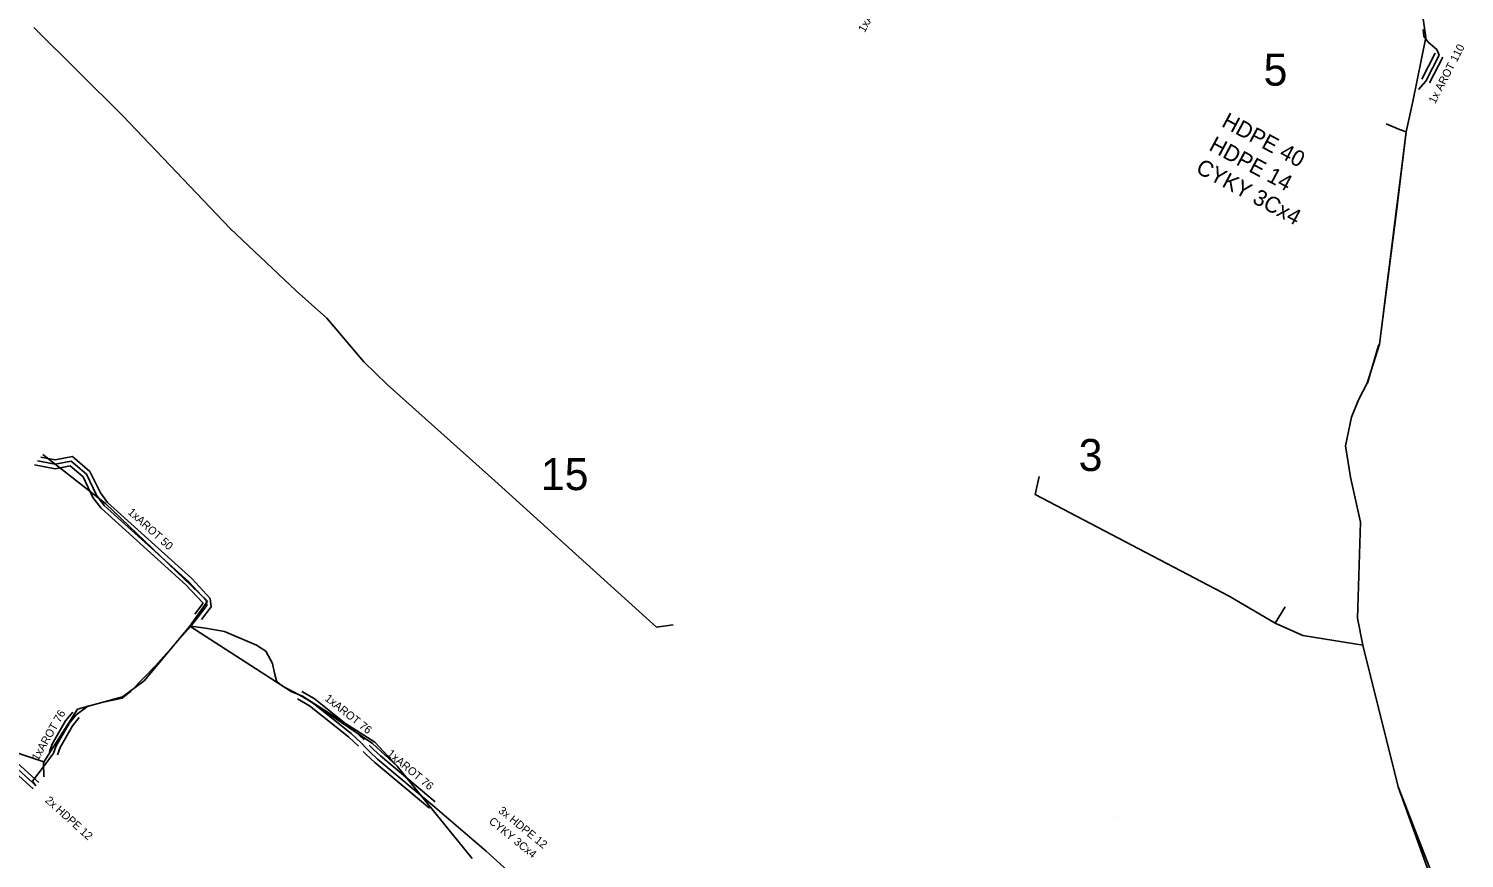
# Model space of a CAD drawing. Extents: x -651943 to -618711, y -1138561 to -1100552.
# Drawn here: x -642611.4 to -642476.9, y -1114571.9 to -1114494.1 of the extents above; entities that cross this region are included whole.
import ezdxf

# ---------------------------------------------------------------- set-up
doc = ezdxf.new("R2010")
doc.units = 0
for name, color, linetype in [('KT optika', 7, 'Continuous'), ('KT trasa', 7, 'Continuous'), ('KT zařízení', 7, 'Continuous'), ('SATT bloky', 7, 'Continuous'), ('SATT stanice', 7, 'Continuous')]:
    doc.layers.add(name, color=color, linetype=linetype)

# ---------------------------------------------------------------- blocks, each defined once
blk = doc.blocks.new('POINT_DISPLAY')
blk.add_line((0, 0), (0, 0))

msp = doc.modelspace()

# ---------------------------------------------------------------- linework, layer by layer
at = {"layer": 'KT optika'}
for p, q in [((-642610.92, -1114493.97), (-642602.59, -1114502.26)), ((-642602.59, -1114502.26), (-642592.51, -1114512.8)), ((-642484.19, -1114502.99), (-642482.93, -1114503.53)), ((-642586.34, -1114518.67), (-642592.51, -1114512.8)), ((-642583.47, -1114521.23), (-642586.34, -1114518.67)), ((-642580.01, -1114525.3), (-642583.47, -1114521.23)), ((-642577.82, -1114527.45), (-642580.01, -1114525.3)), ((-642567.73, -1114536.48), (-642577.82, -1114527.45)), ((-642608.93, -1114534.92), (-642610.57, -1114534.61)), ((-642607.42, -1114534.63), (-642608.93, -1114534.92)), ((-642605.98, -1114535.86), (-642607.42, -1114534.63)), ((-642605.04, -1114537.81), (-642605.98, -1114535.86)), ((-642552.57, -1114550.18), (-642567.73, -1114536.48)), ((-642604.32, -1114538.77), (-642605.04, -1114537.81)), ((-642596.41, -1114545.93), (-642604.32, -1114538.77)), ((-642594.77, -1114547.68), (-642596.41, -1114545.93)), ((-642595.53, -1114549.22), (-642594.72, -1114548.16)), ((-642594.72, -1114548.16), (-642594.77, -1114547.68)), ((-642494.6, -1114549.81), (-642493.66, -1114548.28)), ((-642596.22, -1114550.08), (-642595.53, -1114549.22)), ((-642596.22, -1114550.08), (-642599.52, -1114553.8)), ((-642594.82, -1114550.29), (-642596.22, -1114550.08)), ((-642593.07, -1114550.58), (-642594.82, -1114550.29)), ((-642590.05, -1114551.87), (-642593.07, -1114550.58)), ((-642551.02, -1114549.98), (-642552.57, -1114550.18)), ((-642492, -1114550.98), (-642494.6, -1114549.81)), ((-642486.39, -1114551.88), (-642492, -1114550.98)), ((-642589.18, -1114552.43), (-642590.05, -1114551.87)), ((-642588.55, -1114553.6), (-642589.18, -1114552.43)), ((-642588.36, -1114554.5), (-642588.55, -1114553.6)), ((-642599.52, -1114553.8), (-642601.83, -1114556.19)), ((-642588.19, -1114555.23), (-642588.36, -1114554.5)), ((-642601.83, -1114556.19), (-642602.64, -1114556.84)), ((-642587.62, -1114555.72), (-642588.19, -1114555.23)), ((-642586.01, -1114556.56), (-642587.62, -1114555.72)), ((-642605.86, -1114557.59), (-642606.97, -1114558.4)), ((-642604.28, -1114557.2), (-642605.86, -1114557.59)), ((-642602.64, -1114556.84), (-642604.28, -1114557.2)), ((-642584.87, -1114557.22), (-642586.01, -1114556.56)), ((-642581.17, -1114560.17), (-642584.87, -1114557.22)), ((-642606.97, -1114558.4), (-642607.62, -1114559.21)), ((-642607.62, -1114559.21), (-642608.83, -1114561.32)), ((-642580.23, -1114561.05), (-642581.17, -1114560.17)), ((-642608.83, -1114561.32), (-642609.08, -1114562.01)), ((-642579.78, -1114561.54), (-642580.23, -1114561.05)), ((-642579.44, -1114561.87), (-642579.78, -1114561.54)), ((-642609.08, -1114562.01), (-642610.04, -1114563.3)), ((-642578.71, -1114562.57), (-642579.44, -1114561.87)), ((-642573.57, -1114566.86), (-642578.71, -1114562.57)), ((-642610.04, -1114563.3), (-642611.05, -1114564.61)), ((-642611.05, -1114564.61), (-642610.74, -1114565.06)), ((-642568.52, -1114571.19), (-642573.57, -1114566.86)), ((-642561.43, -1114577.62), (-642568.52, -1114571.19))]:
    msp.add_line(p, q, dxfattribs=at)
msp.add_lwpolyline([(-642479.3, -1114574.88), (-642483.08, -1114565.15), (-642486.39, -1114551.88), (-642486.87, -1114549.35), (-642486.59, -1114540.36), (-642487.54, -1114536.13), (-642487.99, -1114533.19), (-642487.45, -1114530.51), (-642486.8, -1114528.89), (-642485.96, -1114527.32), (-642484.82, -1114523.65), (-642482.31, -1114503.76), (-642481.68, -1114500.92), (-642480.48, -1114494.91), (-642480.84, -1114492.27)], dxfattribs=at)
at = {"layer": 'KT trasa'}
for p, q in [((-642480.48, -1114494.91), (-642480.84, -1114492.27)), ((-642610.92, -1114493.97), (-642602.59, -1114502.26)), ((-642480.67, -1114494.78), (-642480.74, -1114494.17)), ((-642481.68, -1114500.92), (-642480.48, -1114494.91)), ((-642480.27, -1114495.36), (-642480.67, -1114494.78)), ((-642479.46, -1114496.03), (-642480.27, -1114495.36)), ((-642480.48, -1114498.99), (-642479.23, -1114496.57)), ((-642479.23, -1114496.57), (-642479.46, -1114496.03)), ((-642481.15, -1114499.8), (-642480.48, -1114498.99)), ((-642482.31, -1114503.76), (-642481.68, -1114500.92)), ((-642602.59, -1114502.26), (-642592.51, -1114512.8)), ((-642484.19, -1114502.99), (-642482.93, -1114503.53)), ((-642483.27, -1114511.47), (-642482.31, -1114503.76)), ((-642482.31, -1114503.76), (-642482.93, -1114503.53)), ((-642484.82, -1114523.65), (-642483.27, -1114511.47)), ((-642586.34, -1114518.67), (-642592.51, -1114512.8)), ((-642583.47, -1114521.23), (-642586.34, -1114518.67)), ((-642580.01, -1114525.3), (-642583.47, -1114521.23)), ((-642485.95, -1114527.31), (-642484.9, -1114523.78)), ((-642484.9, -1114523.78), (-642484.82, -1114523.65)), ((-642577.82, -1114527.45), (-642580.01, -1114525.3)), ((-642567.73, -1114536.48), (-642577.82, -1114527.45)), ((-642486.8, -1114528.89), (-642485.96, -1114527.32)), ((-642487.45, -1114530.51), (-642486.8, -1114528.89)), ((-642487.99, -1114533.19), (-642487.45, -1114530.51)), ((-642487.54, -1114536.13), (-642487.99, -1114533.19)), ((-642608.93, -1114534.92), (-642610.57, -1114534.61)), ((-642604.2, -1114538.58), (-642610.08, -1114534.01)), ((-642607.42, -1114534.63), (-642608.93, -1114534.92)), ((-642605.98, -1114535.86), (-642607.42, -1114534.63)), ((-642605.04, -1114537.81), (-642605.98, -1114535.86)), ((-642517.08, -1114537.75), (-642516.71, -1114536.06)), ((-642486.59, -1114540.36), (-642487.54, -1114536.13)), ((-642552.57, -1114550.18), (-642567.73, -1114536.48)), ((-642604.32, -1114538.77), (-642605.04, -1114537.81)), ((-642596.41, -1114545.93), (-642604.32, -1114538.77)), ((-642594.65, -1114547.76), (-642604.2, -1114538.58)), ((-642498.91, -1114547.27), (-642517.08, -1114537.75)), ((-642486.87, -1114549.35), (-642486.59, -1114540.36)), ((-642594.77, -1114547.68), (-642596.41, -1114545.93)), ((-642596.3, -1114550.1), (-642594.65, -1114547.76)), ((-642595.53, -1114549.22), (-642594.72, -1114548.16)), ((-642594.72, -1114548.16), (-642594.77, -1114547.68)), ((-642494.6, -1114549.81), (-642498.91, -1114547.27)), ((-642494.6, -1114549.81), (-642493.66, -1114548.28)), ((-642596.22, -1114550.08), (-642595.53, -1114549.22)), ((-642486.39, -1114551.88), (-642486.87, -1114549.35)), ((-642600.57, -1114555.22), (-642596.3, -1114550.1)), ((-642596.22, -1114550.08), (-642599.52, -1114553.8)), ((-642596.3, -1114550.1), (-642586.81, -1114556.23)), ((-642594.82, -1114550.29), (-642596.22, -1114550.08)), ((-642593.07, -1114550.58), (-642594.82, -1114550.29)), ((-642590.05, -1114551.87), (-642593.07, -1114550.58)), ((-642551.02, -1114549.98), (-642552.57, -1114550.18)), ((-642492, -1114550.98), (-642494.6, -1114549.81)), ((-642486.39, -1114551.88), (-642492, -1114550.98)), ((-642589.18, -1114552.43), (-642590.05, -1114551.87)), ((-642483.08, -1114565.15), (-642486.39, -1114551.88)), ((-642588.55, -1114553.6), (-642589.18, -1114552.43)), ((-642588.36, -1114554.5), (-642588.55, -1114553.6)), ((-642599.52, -1114553.8), (-642601.83, -1114556.19)), ((-642588.19, -1114555.23), (-642588.36, -1114554.5)), ((-642601.83, -1114556.19), (-642602.64, -1114556.84)), ((-642602.61, -1114556.72), (-642600.57, -1114555.22)), ((-642587.62, -1114555.72), (-642588.19, -1114555.23)), ((-642586.01, -1114556.56), (-642587.62, -1114555.72)), ((-642586.81, -1114556.23), (-642585.76, -1114556.65)), ((-642605.86, -1114557.59), (-642606.97, -1114558.4)), ((-642606.82, -1114557.86), (-642602.61, -1114556.72)), ((-642604.28, -1114557.2), (-642605.86, -1114557.59)), ((-642602.64, -1114556.84), (-642604.28, -1114557.2)), ((-642584.87, -1114557.22), (-642586.01, -1114556.56)), ((-642585.76, -1114556.65), (-642578.96, -1114560.98)), ((-642579.18, -1114561.09), (-642585.76, -1114556.65)), ((-642581.17, -1114560.17), (-642584.87, -1114557.22)), ((-642610.02, -1114562.86), (-642606.82, -1114557.86)), ((-642606.97, -1114558.4), (-642607.62, -1114559.21)), ((-642607.62, -1114559.21), (-642608.83, -1114561.32)), ((-642580.23, -1114561.05), (-642581.17, -1114560.17)), ((-642610.72, -1114565.04), (-642614.45, -1114561.68)), ((-642608.83, -1114561.32), (-642609.08, -1114562.01)), ((-642579.78, -1114561.54), (-642580.23, -1114561.05)), ((-642579.44, -1114561.87), (-642579.78, -1114561.54)), ((-642579.18, -1114561.09), (-642576.88, -1114563.23)), ((-642576.88, -1114563.23), (-642578.96, -1114560.98)), ((-642609.08, -1114562.01), (-642610.04, -1114563.3)), ((-642610.02, -1114562.86), (-642609.98, -1114564.21)), ((-642578.71, -1114562.57), (-642579.44, -1114561.87)), ((-642573.57, -1114566.86), (-642578.71, -1114562.57)), ((-642610.04, -1114563.3), (-642611.05, -1114564.61)), ((-642576.88, -1114563.23), (-642569.84, -1114571.89)), ((-642611.05, -1114564.61), (-642610.74, -1114565.06)), ((-642479.66, -1114574.63), (-642483.08, -1114565.15)), ((-642568.52, -1114571.19), (-642573.57, -1114566.86)), ((-642561.43, -1114577.62), (-642568.52, -1114571.19))]:
    msp.add_line(p, q, dxfattribs=at)
msp.add_lwpolyline([(-642609.89, -1114562.84), (-642619.45, -1114559.65), (-642643.97, -1114559.65)], dxfattribs=at)
at = {"layer": 'KT zařízení'}
for p, q in [((-642480.84, -1114498.81), (-642479.59, -1114496.39)), ((-642480.12, -1114499.17), (-642478.87, -1114496.75)), ((-642608.93, -1114534.51), (-642610.28, -1114534.26)), ((-642607.31, -1114534.2), (-642608.93, -1114534.51)), ((-642605.66, -1114535.61), (-642607.31, -1114534.2)), ((-642608.93, -1114535.33), (-642610.86, -1114534.96)), ((-642607.53, -1114535.06), (-642608.93, -1114535.33)), ((-642606.3, -1114536.11), (-642607.53, -1114535.06)), ((-642605.38, -1114538.02), (-642606.3, -1114536.11)), ((-642604.69, -1114537.6), (-642605.66, -1114535.61)), ((-642604.03, -1114538.5), (-642604.69, -1114537.6)), ((-642604.62, -1114539.04), (-642605.38, -1114538.02)), ((-642596.13, -1114545.64), (-642604.03, -1114538.5)), ((-642596.69, -1114546.22), (-642604.62, -1114539.04)), ((-642594.39, -1114547.5), (-642596.13, -1114545.64)), ((-642595.06, -1114547.95), (-642596.69, -1114546.22)), ((-642595.85, -1114548.98), (-642595.06, -1114547.95)), ((-642595.21, -1114549.46), (-642594.31, -1114548.28)), ((-642594.31, -1114548.28), (-642594.39, -1114547.5)), ((-642584.65, -1114556.89), (-642585.81, -1114556.21)), ((-642585.09, -1114557.55), (-642586.21, -1114556.91)), ((-642581.44, -1114560.47), (-642585.09, -1114557.55)), ((-642580.9, -1114559.87), (-642584.65, -1114556.89)), ((-642607.95, -1114558.98), (-642609.2, -1114561.16)), ((-642607.28, -1114558.15), (-642607.95, -1114558.98)), ((-642606.66, -1114558.65), (-642607.29, -1114559.44)), ((-642607.29, -1114559.44), (-642608.46, -1114561.48)), ((-642580.5, -1114561.34), (-642581.44, -1114560.47)), ((-642579.96, -1114560.76), (-642580.9, -1114559.87)), ((-642609.2, -1114561.16), (-642609.46, -1114561.87)), ((-642608.46, -1114561.48), (-642608.7, -1114562.15)), ((-642579.8, -1114562.08), (-642580.06, -1114561.83)), ((-642579.08, -1114561.66), (-642579.5, -1114561.25)), ((-642578.45, -1114562.26), (-642579.08, -1114561.66)), ((-642578.97, -1114562.88), (-642579.8, -1114562.08)), ((-642573.83, -1114567.17), (-642578.97, -1114562.88)), ((-642573.31, -1114566.55), (-642578.45, -1114562.26))]:
    msp.add_line(p, q, dxfattribs=at)
for points in [[(-642610.45, -1114564.74), (-642614.19, -1114561.37), (-642616.18, -1114559.85), (-642618.38, -1114557.95), (-642618.97, -1114557.75), (-642620.2, -1114557.28), (-642621.06, -1114557.2), (-642622.77, -1114557.96), (-642630.99, -1114560.06), (-642636.21, -1114561.32), (-642638.26, -1114561.61), (-642641.58, -1114562.54), (-642642.72, -1114562.76), (-642642.9, -1114560.4), (-642643.24, -1114556.07), (-642643.37, -1114553.13), (-642643.98, -1114552.64), (-642645.11, -1114552.72)], [(-642610.99, -1114565.33), (-642614.71, -1114561.99), (-642616.68, -1114560.47), (-642618.78, -1114558.66), (-642619.23, -1114558.51), (-642620.38, -1114558.06), (-642620.92, -1114558.02), (-642622.51, -1114558.72), (-642630.79, -1114560.84), (-642636.06, -1114562.1), (-642638.1, -1114562.39), (-642641.4, -1114563.32), (-642642.86, -1114563.6), (-642643.48, -1114563.36), (-642643.7, -1114560.46), (-642644.04, -1114556.11), (-642644.15, -1114553.53), (-642644.24, -1114553.46), (-642645.06, -1114553.51)]]:
    msp.add_lwpolyline(points, dxfattribs=at)

# ---------------------------------------------------------------- block references
at = {"layer": 'SATT stanice'}
msp.add_blockref('POINT_DISPLAY', (-642509.61, -1114567.97), dxfattribs=at)

# ---------------------------------------------------------------- texts
at = {"layer": 'KT zařízení'}
for s, height, rotation, p in [('1xAROT 40', 0.75, 60.3363, (-642533.07, -1114494.5)), ('1x AROT 110', 0.75, 62.6823, (-642479.6, -1114501.18)), ('HDPE 40', 1.5, 331.8757, (-642499.71, -1114503.2)), ('HDPE 14', 1.5, 331.8757, (-642500.9, -1114505.42)), ('CYKY 3Cx4', 1.5, 331.8757, (-642502.13, -1114507.52)), ('1xAROT 50', 0.75, 317.8472, (-642602.18, -1114539.5)), ('1xAROT 76', 0.75, 321.4355, (-642583.72, -1114556.99)), ('1xAROT 76', 0.75, 60.1729, (-642610.53, -1114562.77)), ('1xAROT 76', 0.75, 320.1517, (-642577.88, -1114562.16)), ('2x HDPE 12', 0.75, 317.973, (-642609.93, -1114566.51)), ('3x HDPE 12', 0.75, 320.7246, (-642567.46, -1114567.5)), ('CYKY 3Cx4', 0.75, 320.7246, (-642568.34, -1114568.51))]:
    msp.add_text(s, height=height, rotation=rotation, dxfattribs=at).set_placement(p)
at = {"layer": 'SATT bloky'}
for s, p in [('5', (-642495.68, -1114499.42)), ('3', (-642513.01, -1114535.55)), ('15', (-642563.41, -1114537.34))]:
    msp.add_text(s, height=3, dxfattribs=at).set_placement(p)

doc.saveas('drawing.dxf')
